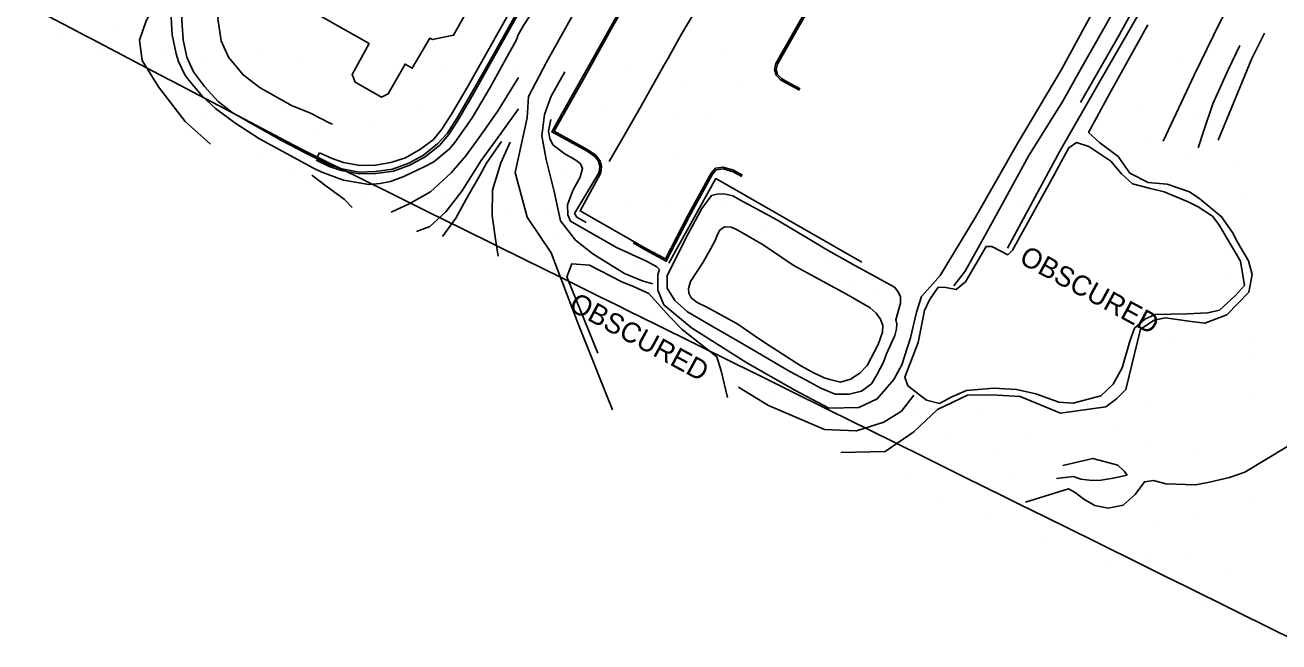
# Model space of a CAD drawing. Extents: x 1497074 to 1501343, y 481943 to 486114.
# Drawn here: x 1498009.1 to 1498383.4, y 483148.3 to 483332.4 of the extents above; entities that cross this region are included whole.
import ezdxf

# ---------------------------------------------------------------- set-up
doc = ezdxf.new("R2010")
doc.units = 0
for name, color, linetype in [('PH Exist DTM Boundary', 7, 'Continuous'), ('PH Exist DTM Breakline', 7, 'Continuous'), ('PH Exist DTM Obscure Area', 7, 'Continuous'), ('PH Exist DTM Obscure Area Text', 7, 'Continuous'), ('PH Exist DTM Point', 7, 'Continuous')]:
    doc.layers.add(name, color=color, linetype=linetype)

msp = doc.modelspace()

# ---------------------------------------------------------------- linework, layer by layer
at = {"layer": 'PH Exist DTM Boundary'}
msp.add_lwpolyline([(1498009.09, 483338.7), (1498022.83, 483331.49), (1498026.93, 483329.33), (1498029.09, 483328.2), (1498040.05, 483322.45), (1498049.09, 483317.7), (1498053.16, 483315.56), (1498060.91, 483311.49), (1498069.09, 483307.2), (1498078.13, 483302.45), (1498089.09, 483296.7), (1498092.78, 483294.76), (1498092.78, 483294.76), (1498099.39, 483291.49), (1498109.09, 483286.7), (1498118.57, 483282.01), (1498129.09, 483276.81), (1498139.85, 483271.49), (1498149.09, 483266.92), (1498158.13, 483262.45), (1498169.09, 483257.03), (1498180.3, 483251.49), (1498186.18, 483248.58), (1498189.09, 483247.15), (1498197.68, 483242.9), (1498209.09, 483237.26), (1498220.76, 483231.49), (1498229.09, 483227.37), (1498237.23, 483223.35), (1498249.09, 483217.49), (1498261.22, 483211.49), (1498269.09, 483207.6), (1498276.79, 483203.79), (1498289.09, 483197.71), (1498301.67, 483191.49), (1498306.64, 483189.04), (1498309.09, 483187.82), (1498320.02, 483182.42), (1498329.09, 483177.94), (1498342.13, 483171.49), (1498349.09, 483168.05), (1498355.9, 483164.69), (1498369.09, 483158.16), (1498382.59, 483151.49), (1498389.09, 483148.28)], dxfattribs=at)
at = {"layer": 'PH Exist DTM Breakline'}
for points in [[(1498159.41, 483311.12), (1498164.77, 483321.34), (1498175.14, 483340.16), (1498186.97, 483361.18), (1498199.39, 483381.85), (1498211.02, 483402.48), (1498221.75, 483420.66), (1498233.01, 483440.86), (1498242.84, 483458.76), (1498250.72, 483471.44), (1498254.65, 483478.17), (1498256.9, 483482.18), (1498259.13, 483485.71)], [(1498276.32, 483456.17), (1498267.23, 483440.15), (1498258.58, 483424.6), (1498249.48, 483408.83), (1498240.71, 483393.06), (1498232.09, 483377.42), (1498223.35, 483361.92), (1498214.5, 483346.31), (1498210.28, 483338.6), (1498205.15, 483329.92), (1498201.01, 483322.58), (1498199.77, 483320.35), (1498192.78, 483307.96), (1498187.85, 483299.32), (1498183.45, 483291.72)], [(1498283.76, 483394.47), (1498289.7, 483404.99), (1498291.29, 483407.98), (1498291.87, 483410.02), (1498291.3, 483411.63), (1498290.03, 483413.01), (1498288.19, 483413.88), (1498286.54, 483413.5), (1498285.11, 483412.56), (1498284.07, 483410.95), (1498276.79, 483397.98), (1498273.94, 483393.07), (1498251.52, 483353.34), (1498233.22, 483320.99), (1498232.75, 483319.21), (1498233.27, 483317.47), (1498234.54, 483316.05), (1498236.15, 483315.17), (1498240.26, 483312.96)], [(1498302.38, 483265.81), (1498317.96, 483294.84), (1498332.74, 483320.42), (1498346.06, 483343.67), (1498357.69, 483364.76), (1498371.07, 483389.46), (1498379.35, 483404.7), (1498381.75, 483409.78), (1498383.06, 483413.57)], [(1498283.33, 483394.72), (1498289.26, 483405.23), (1498290.83, 483408.17), (1498291.34, 483410.01), (1498290.86, 483411.37), (1498289.72, 483412.59), (1498288.06, 483413.22), (1498286.74, 483413.04), (1498285.47, 483412.2), (1498284.5, 483410.69), (1498277.22, 483397.74), (1498274.37, 483392.82), (1498251.96, 483353.09), (1498233.69, 483320.8), (1498233.26, 483319.22), (1498233.72, 483317.72), (1498234.86, 483316.44), (1498236.39, 483315.61), (1498240.5, 483313.4)], [(1498068.16, 483400.23), (1498064.86, 483385.18), (1498061.47, 483367.38), (1498057.62, 483350.97), (1498057.42, 483349.67), (1498056.2, 483341.28), (1498055.9, 483333.94), (1498056.26, 483328.05), (1498057.35, 483322.9), (1498059.32, 483318.51), (1498062.64, 483314.11), (1498066.7, 483309.64), (1498070.89, 483306.35), (1498077.19, 483302.8), (1498085.6, 483298.01), (1498092.73, 483294.31), (1498096.08, 483292.57), (1498097, 483294.32)], [(1498270.76, 483231.03), (1498273.36, 483239.04), (1498275.22, 483246.69), (1498276.7, 483251.45), (1498279.25, 483254.28), (1498282.29, 483257.64), (1498292.78, 483275.08), (1498305.34, 483297.07), (1498318.43, 483319.15), (1498330.34, 483341.04), (1498338.29, 483356.64), (1498344.81, 483368.64), (1498347.77, 483374.42), (1498348.88, 483376.69)], [(1498138.83, 483342.86), (1498140.99, 483336.5), (1498136.99, 483329.41), (1498130.71, 483328.16), (1498129.9, 483328.51), (1498124.65, 483319.55), (1498122.53, 483320.8), (1498117.51, 483311.87), (1498115.5, 483310.94), (1498107.64, 483315.37), (1498106.73, 483317.69), (1498111.84, 483326.89), (1498100.17, 483333.49), (1498094.27, 483336.84), (1498093.58, 483339.93), (1498105.13, 483360.18), (1498107.73, 483364.99)], [(1498078.71, 483364), (1498072.65, 483354.24), (1498069.59, 483347.26), (1498067.64, 483341.32), (1498066.65, 483334.43), (1498067.64, 483327.71), (1498069.77, 483322.88), (1498074.15, 483317.63), (1498079.31, 483313.75), (1498088.86, 483308.34), (1498094.06, 483306.2), (1498100.21, 483303.08), (1498100.83, 483302.89)], [(1498324.17, 483309.37), (1498335.78, 483329.58), (1498347.98, 483352.04)], [(1498056.28, 483348.36), (1498048.17, 483339.48), (1498045.13, 483333.44), (1498043.28, 483327.98), (1498044, 483321.82), (1498048.9, 483314), (1498056.85, 483303.68), (1498064.46, 483296.87)], [(1498348.77, 483297.73), (1498358.05, 483317.49), (1498365.69, 483333.23), (1498372.71, 483346.15)], [(1498165.03, 483343.32), (1498157.83, 483332.3), (1498156.29, 483329.55), (1498155.75, 483328.02), (1498154.76, 483326.26), (1498153.46, 483323.95), (1498148.06, 483313.99), (1498142.52, 483304.78), (1498137.33, 483297.37), (1498135.79, 483295.48), (1498133.45, 483293.55), (1498131.14, 483291.62), (1498128.43, 483290.25), (1498122.18, 483287.24), (1498118.15, 483285.78), (1498115.08, 483285.12), (1498111.71, 483284.89), (1498104.13, 483286.09), (1498097.68, 483288.56), (1498094.76, 483289.96), (1498089.55, 483292.84), (1498079.1, 483298.5), (1498071.66, 483303.21), (1498065.91, 483307.5), (1498062.13, 483310.98), (1498058.02, 483315.98), (1498056.82, 483317.59), (1498054.93, 483321.59), (1498054.19, 483323.88), (1498052.95, 483329.5), (1498052.47, 483338.04)], [(1498286.32, 483254.56), (1498289.74, 483258.99), (1498295.07, 483268.6), (1498301.66, 483280.56), (1498308.69, 483293.54), (1498318.83, 483309.68), (1498324.12, 483319.17), (1498331.51, 483332.09), (1498337.67, 483343.4)], [(1498095.94, 483292.06), (1498099.82, 483290.24), (1498103.56, 483289.02), (1498108.82, 483288.05), (1498113.8, 483288.13), (1498119.08, 483288.84), (1498123.98, 483290.61), (1498128.48, 483293.1), (1498132.79, 483296.47), (1498135.61, 483299.72), (1498138.58, 483304.43), (1498143.12, 483312.34), (1498149.35, 483323.37), (1498156.95, 483336.96)], [(1498096.08, 483292.57), (1498100, 483290.7), (1498103.68, 483289.51), (1498108.86, 483288.55), (1498113.67, 483288.7), (1498118.76, 483289.44), (1498123.6, 483291.16), (1498127.99, 483293.63), (1498132.22, 483296.96), (1498135.07, 483300.11), (1498138.05, 483304.75), (1498142.69, 483312.59), (1498148.9, 483323.62), (1498156.51, 483337.2)], [(1498097, 483294.32), (1498100.74, 483292.57), (1498104.14, 483291.39), (1498109.01, 483290.56), (1498113.72, 483290.58), (1498118.28, 483291.39), (1498122.67, 483292.8), (1498127.15, 483295.35), (1498131.04, 483298.32), (1498133.47, 483301.33), (1498136.35, 483305.8), (1498140.96, 483313.59), (1498147.16, 483324.59), (1498154.76, 483338.17)], [(1498180.26, 483288.11), (1498180.59, 483289.08), (1498180.63, 483290.27), (1498180.24, 483291.79), (1498179.16, 483293.2), (1498176.83, 483294.75), (1498166.3, 483300.56), (1498167.94, 483303.47), (1498175.71, 483317.25), (1498184.12, 483332.35), (1498187.34, 483338.06)], [(1498180.73, 483287.95), (1498181.09, 483288.99), (1498181.13, 483290.33), (1498180.7, 483292.02), (1498179.51, 483293.57), (1498177.09, 483295.18), (1498166.98, 483300.76), (1498168.37, 483303.22), (1498176.15, 483317.01), (1498184.56, 483332.11), (1498187.78, 483337.82)], [(1498252.58, 483204.82), (1498265.83, 483205.16), (1498274.4, 483210.97), (1498281.48, 483217.7), (1498290.41, 483221.91), (1498297.6, 483222.02), (1498306.14, 483221.55), (1498318.18, 483216.62), (1498331.65, 483218.42), (1498334.86, 483220.9), (1498337.69, 483223.6), (1498342.07, 483241.67), (1498346.11, 483244.34), (1498349.53, 483245.07), (1498357.15, 483243.97), (1498361.27, 483243.47), (1498367.84, 483245.92), (1498374.39, 483252.74), (1498375.41, 483258.02), (1498374.33, 483262.05), (1498371, 483267.6), (1498369.46, 483270.49), (1498366.27, 483275.21), (1498359.74, 483280.6), (1498356.71, 483282.61), (1498349.99, 483284.93), (1498344.35, 483285.4), (1498338.87, 483288.26), (1498335.35, 483293.24), (1498329.76, 483297.33), (1498326.56, 483300.39), (1498332.81, 483311.88), (1498344.22, 483332.51)], [(1498365.18, 483298.12), (1498371.14, 483312.35), (1498375.3, 483322.46), (1498379.08, 483329.99)], [(1498371.74, 483326.31), (1498368.2, 483319.05), (1498363.6, 483308.9), (1498360.92, 483300.98), (1498359.24, 483295.8)], [(1498118.33, 483276.62), (1498123.74, 483279.09), (1498130.14, 483282.68), (1498136.25, 483288.34), (1498140.68, 483293.35), (1498144.61, 483298.89), (1498150.11, 483306.68), (1498156.36, 483316.81)], [(1498173.41, 483268.19), (1498168.94, 483273.99), (1498167.07, 483282.77), (1498164.59, 483292.3), (1498163.3, 483299.36), (1498164.13, 483305.73), (1498166.17, 483311.2), (1498170.19, 483318.44)], [(1498166.09, 483264.41), (1498158.95, 483275.07), (1498155.34, 483288.44), (1498158.92, 483304.78), (1498159.41, 483311.12)], [(1498156.34, 483307.44), (1498151.15, 483300.04), (1498145.2, 483292), (1498139.44, 483282.82), (1498134.65, 483276.72), (1498129.88, 483272.34), (1498125.95, 483270.78)], [(1498171.86, 483273.91), (1498171.15, 483275.77), (1498171, 483278.73), (1498172.55, 483283.06), (1498174.81, 483287.07), (1498175.52, 483289.6), (1498174.88, 483291.04), (1498173.78, 483291.92), (1498171.8, 483293.06), (1498170.33, 483293.91), (1498166.63, 483296.71), (1498165.73, 483298.54), (1498165.29, 483300.79), (1498166.05, 483304.2)], [(1498133.74, 483269.28), (1498137.63, 483274.78), (1498140.7, 483280.22), (1498144.92, 483287.7), (1498146.86, 483291.16), (1498151.31, 483297.68)], [(1498150.26, 483263.44), (1498149.63, 483267.8), (1498148.53, 483275.6), (1498148.62, 483283.1), (1498151.09, 483291.34), (1498153.87, 483297.44)], [(1498180.73, 483287.95), (1498174.77, 483276.95), (1498194.62, 483265.67), (1498200.26, 483262.62), (1498206.86, 483275.43), (1498213.84, 483288.27), (1498215.15, 483289.67), (1498217.51, 483290.06), (1498220.6, 483289.12), (1498223.27, 483287.62)], [(1498094.71, 483287.65), (1498099.23, 483284.11), (1498104.3, 483280.45), (1498106.75, 483277.97)], [(1498180.26, 483288.11), (1498173.12, 483276.2), (1498173.79, 483275.08), (1498176.54, 483273.52)], [(1498190.6, 483267.38), (1498194.38, 483265.23), (1498200.47, 483261.94), (1498207.31, 483275.19), (1498214.25, 483287.97), (1498215.4, 483289.21), (1498217.47, 483289.55), (1498220.41, 483288.66), (1498223.03, 483287.18)], [(1498201.22, 483261.39), (1498215.33, 483286.63), (1498258.84, 483261.65)], [(1498200.77, 483257.57), (1498206.44, 483269), (1498211.13, 483277.63), (1498213.95, 483281.53), (1498215.59, 483281.92), (1498217.63, 483282.06), (1498220.37, 483281.42), (1498222.46, 483280.28), (1498230.19, 483276.08), (1498233.46, 483274.3), (1498244.35, 483267.79), (1498248.07, 483265.51), (1498256.96, 483260.59), (1498260.47, 483258.69), (1498268.57, 483254.16), (1498269.71, 483252.83), (1498270.38, 483251.32), (1498270.42, 483249.41), (1498269.05, 483244.43), (1498269.28, 483243.14), (1498269.22, 483241.74), (1498268.75, 483239.74), (1498266.26, 483234.3), (1498265.33, 483231.83), (1498263.33, 483228.02), (1498261.75, 483225.33), (1498258.73, 483223.15), (1498255.07, 483222.23), (1498250.88, 483222.25), (1498246.65, 483224.02), (1498242.28, 483226.4), (1498237.41, 483229.04), (1498224.34, 483236.7), (1498214.02, 483242.67), (1498206.82, 483246.87), (1498203.08, 483250.21), (1498200.77, 483253.92), (1498200.77, 483257.57)], [(1498171.86, 483273.91), (1498185.65, 483266.06), (1498194.57, 483261.92), (1498197.65, 483260.25), (1498198.43, 483259.43)], [(1498222.3, 483270.87), (1498229.41, 483266.83), (1498238.38, 483260.76), (1498244.92, 483257.21), (1498254.27, 483252.12), (1498261.4, 483248.06), (1498263.11, 483246.39), (1498264.4, 483244.61), (1498265.1, 483242.78), (1498265.04, 483240.71), (1498263.73, 483237.08), (1498260.46, 483230.84), (1498258.3, 483228.54), (1498255.44, 483226.76), (1498252.52, 483225.79), (1498249.31, 483226.58), (1498247.64, 483227.13), (1498244.14, 483228.86), (1498240.7, 483230.73), (1498229.56, 483237.89), (1498226.76, 483239.78), (1498221.82, 483243.12), (1498219, 483244.78), (1498212.75, 483248.1), (1498209.7, 483249.63), (1498207.91, 483251.01), (1498207.2, 483252.41), (1498207.1, 483253.83), (1498207.69, 483255.84), (1498211.53, 483261.62), (1498213.78, 483265.73), (1498215.06, 483268.13), (1498215.78, 483269.94), (1498216.48, 483271.25), (1498217.89, 483272.19), (1498219.86, 483272.15), (1498221.06, 483271.57), (1498222.3, 483270.87)], [(1498173.41, 483268.19), (1498178.58, 483264.12), (1498187.97, 483258.26), (1498193.64, 483256), (1498196.5, 483255.19)], [(1498184.41, 483217.52), (1498174.18, 483243.24), (1498166.09, 483264.41)], [(1498270.76, 483231.03), (1498268.37, 483226.64), (1498263.45, 483220.85), (1498257.92, 483218.24), (1498248.98, 483218.08), (1498238.89, 483223.41), (1498224.53, 483231.55), (1498208, 483242), (1498199.79, 483248.93), (1498197.99, 483253.26), (1498197.99, 483258.01), (1498198.43, 483259.43)], [(1498222.01, 483224.38), (1498231.01, 483218.91), (1498247.71, 483211.72), (1498257.3, 483211.34), (1498265.4, 483213.9), (1498270.67, 483217.15), (1498274.35, 483221.98)], [(1498307.71, 483189.96), (1498320.55, 483193.94), (1498322.55, 483192.87), (1498325.11, 483190.93), (1498328.41, 483189.04), (1498332.39, 483188.25), (1498336.86, 483189.07), (1498340.49, 483192.32), (1498343.22, 483196.1), (1498345.93, 483196.47), (1498349.58, 483195.48), (1498358.5, 483195.13), (1498362.63, 483195.99), (1498368.66, 483197.33), (1498373.14, 483198.98), (1498385.21, 483206.21), (1498394.8, 483212.47), (1498398.72, 483213.13), (1498405.17, 483213.13), (1498412.93, 483211.42), (1498422.54, 483209.67), (1498428.63, 483209.29), (1498433.74, 483209.45)], [(1498318.83, 483200.9), (1498327.79, 483203.06), (1498335.32, 483201.01), (1498337.3, 483199.15), (1498338.11, 483198.1)], [(1498316.99, 483197.1), (1498322.03, 483197.64), (1498324.28, 483196.91), (1498327.62, 483196.48), (1498330.27, 483196.61), (1498333.93, 483197.13), (1498338.11, 483198.1)]]:
    msp.add_lwpolyline(points, dxfattribs=at)
at = {"layer": 'PH Exist DTM Obscure Area'}
for points in [[(1498365.46, 483272.89), (1498371.91, 483261.97), (1498373.13, 483254.73), (1498370.43, 483251.69), (1498365.61, 483247.28), (1498362.12, 483246.57), (1498356, 483246.19), (1498346.42, 483245.99), (1498343.36, 483244.64), (1498340.29, 483241.91), (1498338.86, 483238.03), (1498336.55, 483230.1), (1498333.89, 483225.21), (1498330.24, 483221.76), (1498321.96, 483219.54), (1498317.62, 483219.84), (1498310.79, 483222.38), (1498305.08, 483223.63), (1498298.24, 483224.02), (1498290.13, 483223.31), (1498285.7, 483221.44), (1498282.04, 483219.5), (1498278.15, 483220.44), (1498272.62, 483224.77), (1498271.72, 483227.34), (1498275.7, 483237.7), (1498277.58, 483247.21), (1498279.04, 483250.43), (1498281.67, 483254.18), (1498283.92, 483254.09), (1498287.04, 483253.45), (1498289.81, 483255.83), (1498296, 483266.32), (1498297.66, 483266.31), (1498302.41, 483263.85), (1498303.84, 483265.23), (1498316.16, 483287.56), (1498318.49, 483291.85), (1498320.66, 483295.8), (1498322.98, 483297.33), (1498326.66, 483296.22), (1498333.17, 483291.79), (1498336.34, 483288.03), (1498339.64, 483285.05), (1498345, 483283.67), (1498349.09, 483282.68), (1498356.26, 483279.67), (1498359.3, 483278.2), (1498363.54, 483275.35), (1498365.46, 483272.89)], [(1498180.04, 483234.51), (1498170.78, 483257.3), (1498172.28, 483261.16), (1498177.53, 483260.8), (1498187.2, 483255.79), (1498190.9, 483254.27), (1498195.33, 483252.3), (1498201.41, 483245.39), (1498205.23, 483241.55), (1498215.61, 483233.39), (1498216.88, 483229.25), (1498218.78, 483221.27)]]:
    msp.add_lwpolyline(points, dxfattribs=at)
at = {"layer": 'PH Exist DTM Point'}
for p, q in [((1498035.84, 483332.17), (1498035.84, 483332.17)), ((1498020.44, 483329.44), (1498020.44, 483329.44)), ((1498079.42, 483323.98), (1498079.42, 483323.98)), ((1498218.91, 483324.34), (1498218.91, 483324.34)), ((1498032.35, 483323.34), (1498032.35, 483323.34)), ((1498049.43, 483323.5), (1498049.43, 483323.5)), ((1498063.45, 483322.98), (1498063.45, 483322.98)), ((1498092.24, 483320.83), (1498092.24, 483320.83)), ((1498322.38, 483321.78), (1498322.38, 483321.78)), ((1498354.44, 483323.08), (1498354.44, 483323.08)), ((1498133.85, 483319.36), (1498133.85, 483319.36)), ((1498154.49, 483319.68), (1498154.49, 483319.68)), ((1498188.44, 483319.31), (1498188.44, 483319.31)), ((1498206.78, 483314.05), (1498206.78, 483314.05)), ((1498223.55, 483314.54), (1498223.55, 483314.54)), ((1498149.02, 483310.26), (1498149.02, 483310.26)), ((1498062.12, 483305.48), (1498062.12, 483305.48)), ((1498126.19, 483308.63), (1498126.19, 483308.63)), ((1498181.95, 483307.75), (1498181.95, 483307.75)), ((1498341.72, 483307.62), (1498341.72, 483307.62)), ((1498358.07, 483305.22), (1498358.07, 483305.22)), ((1498111.55, 483302.11), (1498111.55, 483302.11)), ((1498202.39, 483304.16), (1498202.39, 483304.16)), ((1498214.12, 483304.19), (1498214.12, 483304.19)), ((1498095.85, 483299.81), (1498095.85, 483299.81)), ((1498078.48, 483294.35), (1498078.48, 483294.35)), ((1498203.71, 483294.26), (1498203.71, 483294.26)), ((1498306.16, 483293.92), (1498306.16, 483293.92)), ((1498344.64, 483297.04), (1498344.64, 483297.04)), ((1498134.44, 483290.78), (1498134.44, 483290.78)), ((1498355.66, 483293.68), (1498355.66, 483293.68)), ((1498369.37, 483291.54), (1498369.37, 483291.54)), ((1498087.84, 483288.93), (1498087.84, 483288.93)), ((1498169.89, 483289.51), (1498169.89, 483289.51)), ((1498110.81, 483281.3), (1498110.81, 483281.3)), ((1498121.05, 483282.21), (1498121.05, 483282.21)), ((1498133.33, 483281.93), (1498133.33, 483281.93)), ((1498189.29, 483279.28), (1498189.29, 483279.28)), ((1498201.01, 483280.14), (1498201.01, 483280.14)), ((1498305.79, 483279.82), (1498305.79, 483279.82)), ((1498372.39, 483281.58), (1498372.39, 483281.58)), ((1498153.74, 483277.2), (1498153.74, 483277.2)), ((1498163.99, 483277.6), (1498163.99, 483277.6)), ((1498218.54, 483277.84), (1498218.54, 483277.84)), ((1498230.46, 483271.45), (1498230.46, 483271.45)), ((1498294.31, 483274.2), (1498294.31, 483274.2)), ((1498143.13, 483268.55), (1498143.13, 483268.55)), ((1498168.02, 483269.1), (1498168.02, 483269.1)), ((1498156.95, 483265.06), (1498156.95, 483265.06)), ((1498290.24, 483266.04), (1498290.24, 483266.04)), ((1498191.19, 483260.86), (1498191.19, 483260.86)), ((1498205.89, 483260.61), (1498205.89, 483260.61)), ((1498247.81, 483261.48), (1498247.81, 483261.48)), ((1498368.55, 483258.18), (1498368.55, 483258.18)), ((1498257.11, 483255.95), (1498257.11, 483255.95)), ((1498264.14, 483252.3), (1498264.14, 483252.3)), ((1498216.26, 483243.93), (1498216.26, 483243.93)), ((1498351.09, 483239.34), (1498351.09, 483239.34)), ((1498374.32, 483239.58), (1498374.32, 483239.58)), ((1498374.53, 483233.01), (1498374.53, 483233.01)), ((1498271.04, 483223.33), (1498271.04, 483223.33)), ((1498232.23, 483222.38), (1498232.23, 483222.38)), ((1498375.07, 483220.64), (1498375.07, 483220.64)), ((1498274.08, 483216.42), (1498274.08, 483216.42)), ((1498295.3, 483216.16), (1498295.3, 483216.16)), ((1498344.74, 483218.74), (1498344.74, 483218.74)), ((1498252.94, 483214.92), (1498252.94, 483214.92)), ((1498333.94, 483212.9), (1498333.94, 483212.9)), ((1498284.76, 483209.8), (1498284.76, 483209.8)), ((1498309.57, 483208.76), (1498309.57, 483208.76)), ((1498344.97, 483208.26), (1498344.97, 483208.26)), ((1498298.46, 483205.29), (1498298.46, 483205.29)), ((1498357.45, 483204.25), (1498357.45, 483204.25)), ((1498273.75, 483196.83), (1498273.75, 483196.83)), ((1498302.5, 483198.52), (1498302.5, 483198.52)), ((1498281.8, 483191.54), (1498281.8, 483191.54)), ((1498375.33, 483189.52), (1498375.33, 483189.52)), ((1498296.06, 483186.64), (1498296.06, 483186.64)), ((1498357.61, 483185.69), (1498357.61, 483185.69)), ((1498346.03, 483184.64), (1498346.03, 483184.64)), ((1498313.25, 483178.47), (1498313.25, 483178.47)), ((1498343.69, 483174.26), (1498343.69, 483174.26)), ((1498355.82, 483174.14), (1498355.82, 483174.14)), ((1498331.97, 483172), (1498331.97, 483172)), ((1498368.39, 483170.14), (1498368.39, 483170.14)), ((1498360.71, 483159.89), (1498360.71, 483159.89)), ((1498374.8, 483152.26), (1498374.8, 483152.26))]:
    msp.add_line(p, q, dxfattribs=at)

# ---------------------------------------------------------------- texts
at = {"layer": 'PH Exist DTM Obscure Area Text'}
for p in [(1498305.48, 483261.59), (1498171.06, 483247.58)]:
    msp.add_text('OBSCURED', height=6, rotation=331.4703, dxfattribs=at).set_placement(p)

doc.saveas('drawing.dxf')
